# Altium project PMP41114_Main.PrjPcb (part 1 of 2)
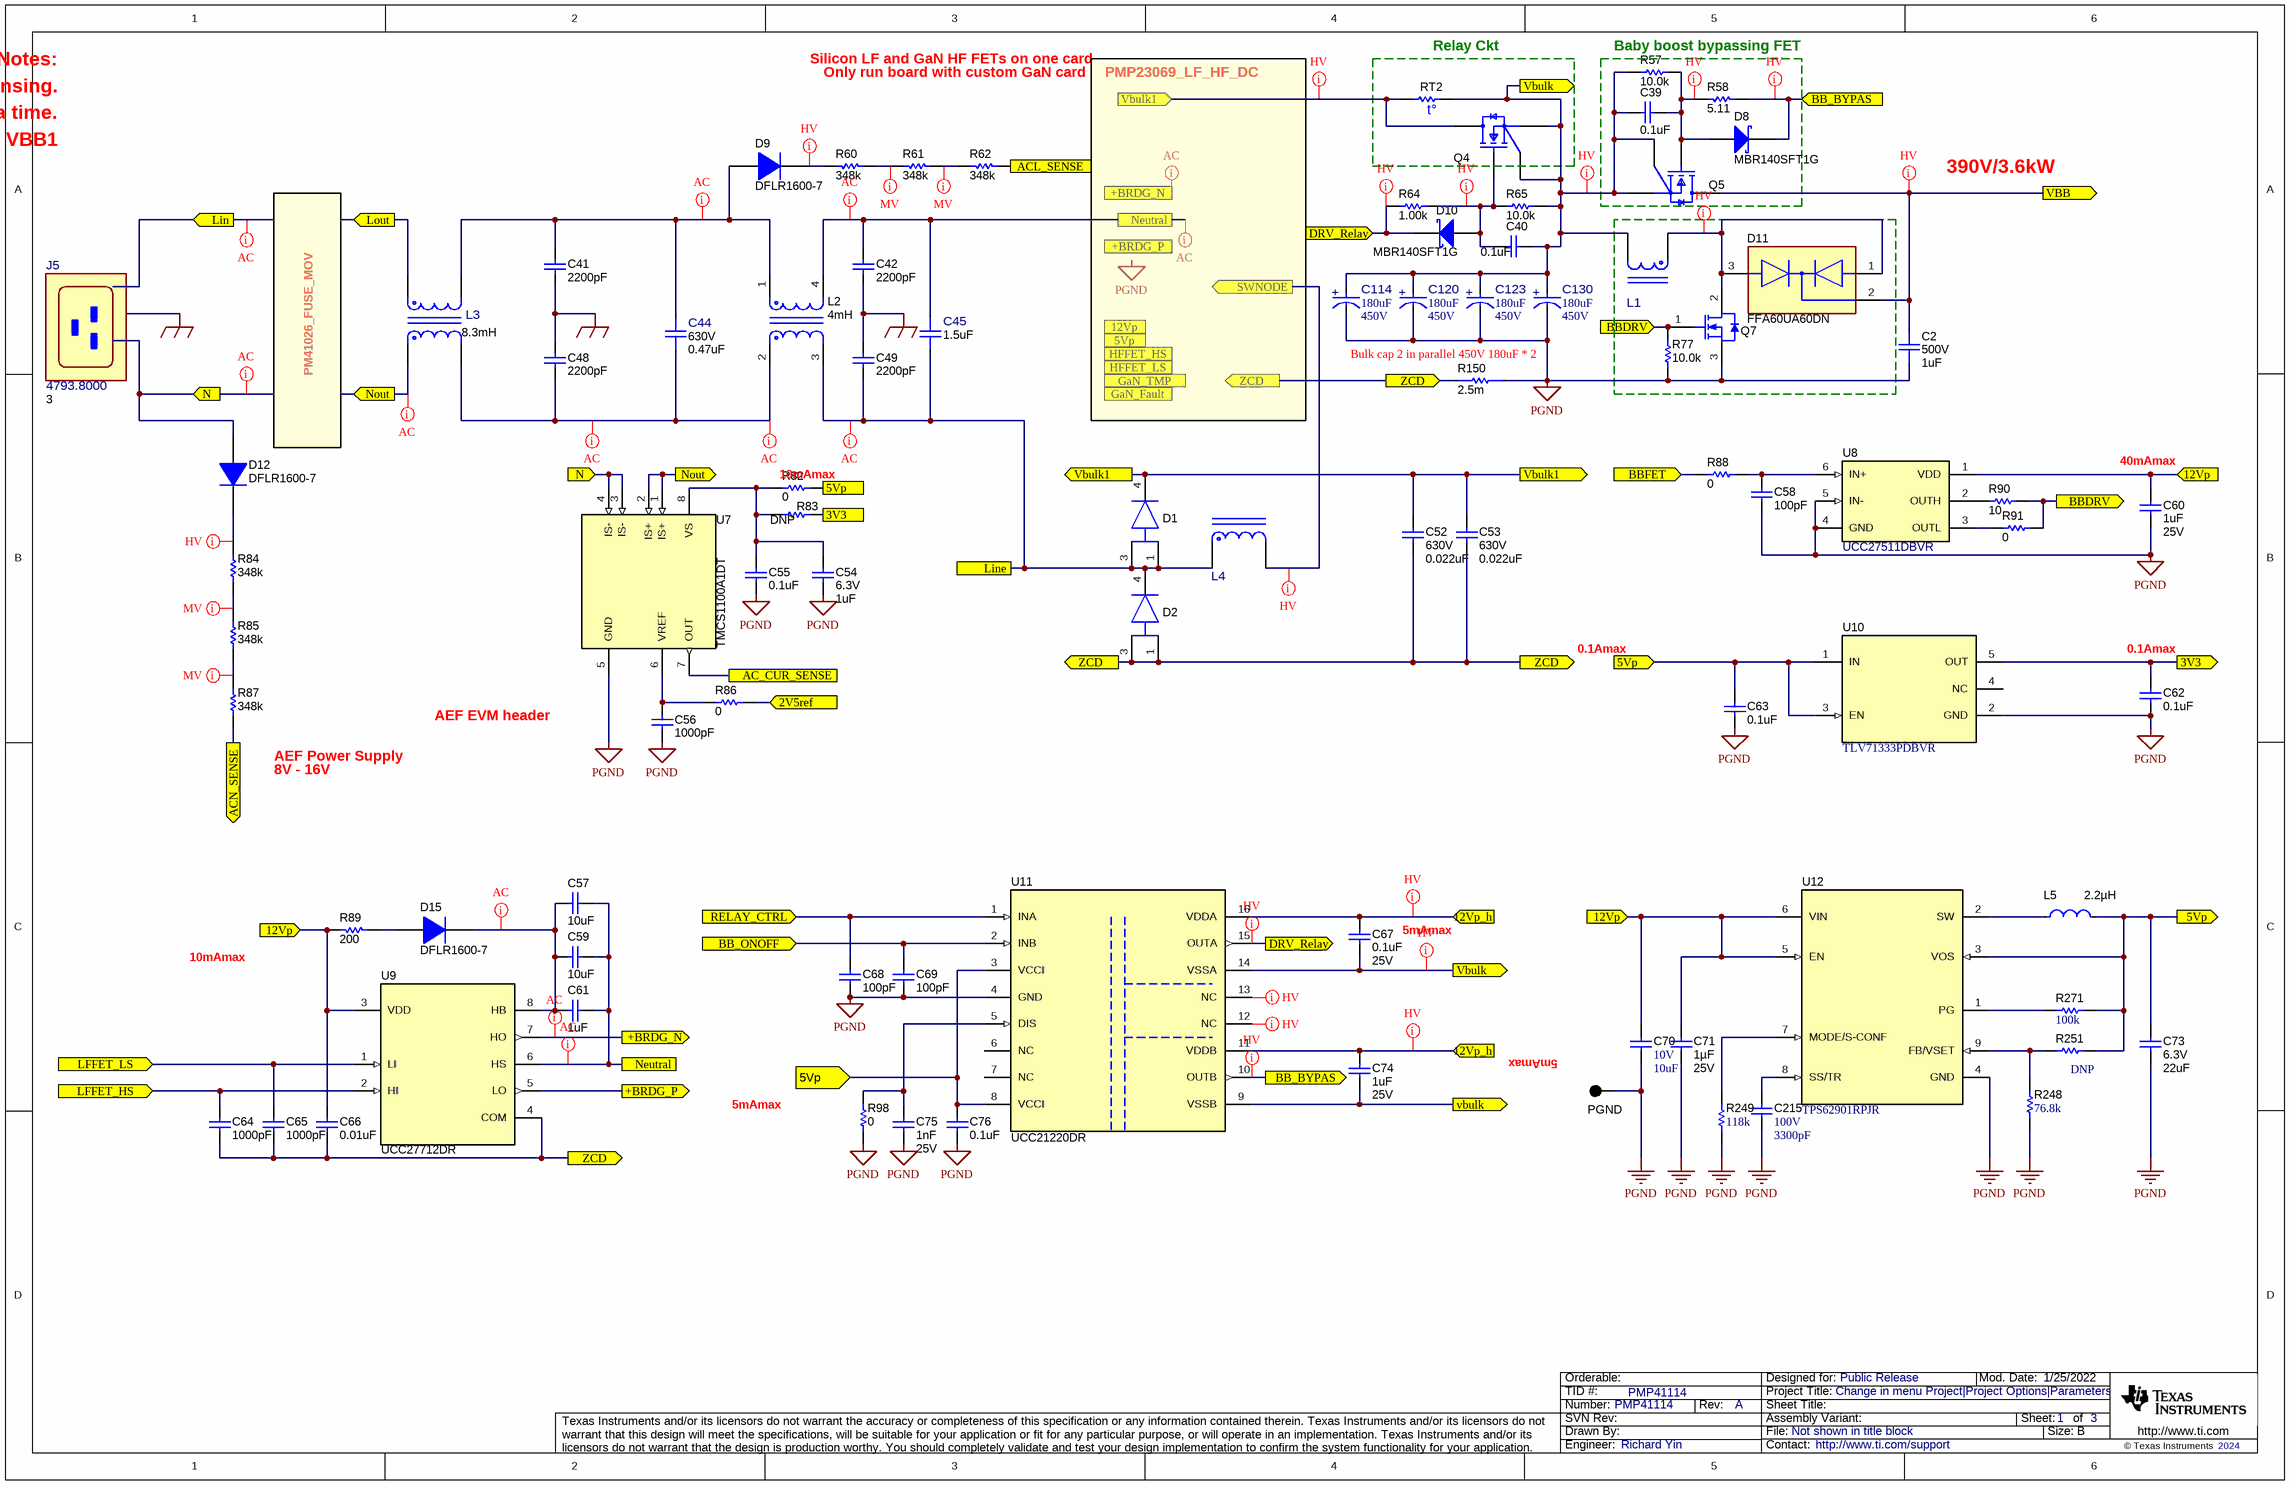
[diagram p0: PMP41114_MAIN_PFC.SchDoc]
CopyrightYear: 2024; PCB_Layout: Richard Yin; PCB_Rev: A; PRJ_Customer: Public Release; PRJ_Engineer: Richard Yin; PRJ_Number: PMP41114; PRJ_Title: Change in menu Project|Project Options|Parameters; SCH_Rev: A; TechSupport: http://www.ti.com/support; TID: PMP41114
3 sheets, 192 parts. Net scope: flat (ports and power ports of the same name join across sheets).
Board file: PMP41114_MAIN_PCB.PcbDoc
Sheets:
  PMP41114_MAIN_PFC.SchDoc
  PMP41114_MAIN_PFC_Control.SchDoc
  PMP41114_MAIN_LLC.SchDoc

## Sheet PMP41114_MAIN_PFC.SchDoc
size 431 x 279 mm; Date: Not shown in title block; ApprovedBy: Not shown in title block; CheckedBy: Not shown in title block; Author: Not shown in title block; CompanyName: Not shown in title block; Engineer: Not shown in title block; Organization: Not shown in title block; Address1: Not shown in title block; Address2: Not shown in title block; Address3: Not shown in title block; Address4: Not shown in title block; DocumentNumber: 1; Revision: Use project parameter SCH_Rev; SheetNumber: 1; SheetTotal: 3; PageSetup: Record=PageOptions¦CenterHorizontal=True¦CenterVertical=True¦PrintScale=1.00¦XCorrection=1.00¦YCorrection=1.00¦PrintKind=0¦BorderSize=5000000¦LeftOffset=0¦BottomOffset=0¦Orientation=2¦PaperLength=1000¦PaperWidth=1000¦Scale=100¦PaperSource=15¦PrintQuality=600¦MediaType=1¦DitherType=10¦PaperKind=Letter¦PrintScaleMode=1

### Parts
C2  VDC_V: 500V  ValueDisplayed: 1uF  [FP-B58031U5105M062_SMD2-MFG]  (hidden comment: B58031U5105M062)
C39  ValueDisplayed: 0.1uF  [0603]  (hidden comment: 06033C104JAT2A)
C40  ValueDisplayed: 0.1uF  [0603]  (hidden comment: 06033C104JAT2A)
C41  ValueDisplayed: 2200pF  [E_900x700x900]  (hidden comment: DE6E3KJ222MN3A)
C42  ValueDisplayed: 2200pF  [E_900x700x900]  (hidden comment: DE6E3KJ222MN3A)
C44  VDC_V: 630V  ValueDisplayed: 0.47uF  [FP-F862BY474K310Z_RADIAL-MFG]  (hidden comment: F862BY474K310Z)
C45  ValueDisplayed: 1.5uF  [FP-890334026030_RADIAL-MFG]  (hidden comment: 890334026030)
C48  ValueDisplayed: 2200pF  [E_900x700x900]  (hidden comment: DE6E3KJ222MN3A)
C49  ValueDisplayed: 2200pF  [E_900x700x900]  (hidden comment: DE6E3KJ222MN3A)
C52  VDC_V: 630V  ValueDisplayed: 0.022uF  [1210_150]  (hidden comment: GRM32QR72J223KW01L)
C53  VDC_V: 630V  ValueDisplayed: 0.022uF  [1210_150]  (hidden comment: GRM32QR72J223KW01L)
C54  VDC_V: 6.3V  ValueDisplayed: 1uF  [0402]  (hidden comment: GRM155R70J105KA12D)
C55  ValueDisplayed: 0.1uF  [0402]  (hidden comment: GRM155R70J104KA01D)
C56  ValueDisplayed: 1000pF  [0402]  (hidden comment: GRM155R60J102KA01D)
C57  ValueDisplayed: 10uF  [0805_HV]  (hidden comment: 0805YD106MAT2A)
C58  ValueDisplayed: 100pF  [0402]  (hidden comment: 0402YC101KAT2A)
C59  ValueDisplayed: 10uF  [0805_HV]  (hidden comment: 0805YD106MAT2A)
C60  ValueDisplayed: 1uF  Value2: 25V  [1206]  (hidden comment: C3216X7R1E105K085AA)
C61  ValueDisplayed: 1uF  [0603]  (hidden comment: C1608X7R1E105K080AB)
C62  ValueDisplayed: 0.1uF  [0402]  (hidden comment: GRM155R70J104KA01D)
C63  ValueDisplayed: 0.1uF  [0402]  (hidden comment: GRM155R70J104KA01D)
C64  ValueDisplayed: 1000pF  [0603]  (hidden comment: 06035A102KAT2A)
C65  ValueDisplayed: 1000pF  [0603]  (hidden comment: 06035A102KAT2A)
C66  ValueDisplayed: 0.01uF  [0603]  (hidden comment: C0603X103K5RACTU)
C67  ValueDisplayed: 0.1uF  VDC_V: 25V  [1206_190]  (hidden comment: C1206H104J3GACTU)
C68  ValueDisplayed: 100pF  [0402]  (hidden comment: 0402YC101KAT2A)
C69  ValueDisplayed: 100pF  [0402]  (hidden comment: 0402YC101KAT2A)
C70  VDC_V: 10V  ValueDisplayed: 10uF  [1206]  (hidden comment: C3216X7R1A106M160AC)
C71  Cap_F: 1µF  VDC_V: 25V  [0805_HV]  (hidden comment: C0805C105K3RACTU)
C73  VDC_V: 6.3V  ValueDisplayed: 22uF  [0805_HV]  (hidden comment: CL21A226KQQNNNE)
C74  ValueDisplayed: 1uF  Value2: 25V  [1206]  (hidden comment: C3216X7R1E105K085AA)
C75  Cap_F: 1nF  VDC_V: 25V  [0603]  (hidden comment: GRM188R71E102KA01D)
C76  ValueDisplayed: 0.1uF  [0402]  (hidden comment: 0402YC104KAT2A)
C114  ValueDisplayed: 180uF  VDC_V: 450V  [FP-450HXW180MEFR16X50_RADIAL-MFG]  (hidden comment: 450HXW180MEFR16X50)
C120  ValueDisplayed: 180uF  VDC_V: 450V  [FP-450HXW180MEFR16X50_RADIAL-MFG]  (hidden comment: 450HXW180MEFR16X50)
C123  ValueDisplayed: 180uF  VDC_V: 450V  [FP-450HXW180MEFR16X50_RADIAL-MFG]  (hidden comment: 450HXW180MEFR16X50)
C130  ValueDisplayed: 180uF  VDC_V: 450V  [FP-450HXW180MEFR16X50_RADIAL-MFG]  (hidden comment: 450HXW180MEFR16X50)
C215  VDC_V: 100V  ValueDisplayed: 3300pF  [0402]  (hidden comment: GRM155R72A332KA01D)
D1  VS-15EVL06-M3/I  [FP-VS-15AWL06FN-M3_D-PAK (TO-252AA)-MFG]  (value not drawn)
D2  VS-15EVL06-M3/I  [FP-VS-15AWL06FN-M3_D-PAK (TO-252AA)-MFG]  (value not drawn)
D8  MBR140SFT1G  [SOD-123FL]
D9  DFLR1600-7  [PowerDI123]
D10  MBR140SFT1G  [SOD-123FL]
D11  FFA60UA60DN  [FP-FFA60UA60DN_SC-65-MFG]
D12  DFLR1600-7  [PowerDI123]
D15  DFLR1600-7  [PowerDI123]
J5  4793.8000  PinCount: 3  [FP-4793.8000_RCPT_IEC320-C20-MFG]
L1  PAL6598.104NLT  [FP-PAL6281.104NL_PTH_20MM5_11MM0-MFG]  (value not drawn)
L2  Ind_H: 4mH  [FP-PAC6270NL_PTH_TRANSFORMER_30MM0_19MM0-MFG]  (hidden comment: PAC6596NL)
L3  Ind_H: 8.3mH  [FP-PAC6280NL_PTH_25MM0_12MM5-MFG]  (hidden comment: PAC6597NL)
L4  PAL6585  [FP-PAL6269NL_PTH_32MM0_27MM8-MFG]  (value not drawn)
L5  Ind_H: 2.2µH  [FP-74438336010_SMD2-MFG]  (hidden comment: 74438336022)
PGND  5001  [Keystone5001]  (value not drawn)
Q4  IPT60R022S7XTMA1  [FP-IPT60R080G7XTMA1_HSOF-8-MFG]  (value not drawn)
Q5  IPT60R022S7XTMA1  [FP-IPT60R080G7XTMA1_HSOF-8-MFG]  (value not drawn)
Q7  IPP60R060P7XKSA1  [TO-220AB_100mil]  (value not drawn)
R57  ValueDisplayed: 10.0k  [0603]  (hidden comment: CRCW060310K0FKEA)
R58  ValueDisplayed: 5.11  [0603]  (hidden comment: CRCW06035R11FKEA)
R60  ValueDisplayed: 348k  [1206]  (hidden comment: RC1206FR-07348KL)
R61  ValueDisplayed: 348k  [1206]  (hidden comment: RC1206FR-07348KL)
R62  ValueDisplayed: 348k  [1206]  (hidden comment: RC1206FR-07348KL)
R64  ValueDisplayed: 1.00k  [1206]  (hidden comment: ERJ-8ENF1001V)
R65  ValueDisplayed: 10.0k  [0603]  (hidden comment: CRCW060310K0FKEA)
R77  ValueDisplayed: 10.0k  [0603]  (hidden comment: CRCW060310K0FKEA)
R82  ValueDisplayed: 0  [0402]  (hidden comment: RC0402JR-070RL)
R83  value DNP  [0402]  (hidden comment: RC0402JR-070RL)
R84  ValueDisplayed: 348k  [1206]  (hidden comment: RC1206FR-07348KL)
R85  ValueDisplayed: 348k  [1206]  (hidden comment: RC1206FR-07348KL)
R86  ValueDisplayed: 0  [0402]  (hidden comment: RC0402JR-070RL)
R87  ValueDisplayed: 348k  [1206]  (hidden comment: RC1206FR-07348KL)
R88  ValueDisplayed: 0  [0402]  (hidden comment: CRCW04020000Z0ED)
R89  value 200  [0603]  (hidden comment: CRCW0603200RFKEA)
R90  ValueDisplayed: 10  [0603]  (hidden comment: CRCW060310R0JNEAHP)
R91  ValueDisplayed: 0  [0603]  (hidden comment: CRCW06030000Z0EA)
R98  ValueDisplayed: 0  [0603]  (hidden comment: CRCW06030000Z0EA)
R150  value 2.5m  [FP-WSLP3921L1000FEA_3921-MFG]  (hidden comment: WSLP39212L500FEA)
R248  ValueDisplayed: 76.8k  [0402]  (hidden comment: CRCW040276K8FKED)
R249  ValueDisplayed: 118k  [0603]  (hidden comment: CRCW0603118KFKEA)
R251  value DNP  [0402]  (hidden comment: RC0402FR-07100KL)
R271  ValueDisplayed: 100k  [0402]  (hidden comment: RC0402FR-07100KL)
RT2  B59751B0120A070  [TDK_B751]  (value not drawn)
U7  TMCS1100A1DT  [D0008A_N]
U8  UCC27511DBVR  [DBV0006A_N]
U9  UCC27712DR  [D0008A_N]
U10  TLV71333PDBVR  [DBV0005A_N]
U11  UCC21220DR  [D0016B]
U12  TPS62901RPJR  [RPJ0009A]

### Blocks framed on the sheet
Relay Ckt: Q4 RT2
Baby boost bypassing FET: C39 D8 Q5 R57 R58

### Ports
2V5ref (in), 3V3 (in), 3V3 (out), 5Vp (in), 5Vp (out), 12Vp (in), 12Vp_h (in), +BRDG_N (in), +BRDG_N (out), +BRDG_P (in), +BRDG_P (out), AC_CUR_SENSE, ACL_SENSE (out), ACN_SENSE (out), BB_BYPAS (in), BB_BYPAS (out), BB_ONOFF (in), BBDRV (in), BBDRV (out), BBFET (in), DRV_Relay (in), DRV_Relay (out), GaN_Fault (out), GaN_TMP (out), HFFET_HS (in), HFFET_LS (in), LFFET_HS (in), LFFET_LS (in), Lin (in), Line, Lout (in), N (in), Neutral, Nout (in), Nout (out), RELAY_CTRL (in), SWNODE (out), VBB (out), Vbulk1 (in), Vbulk1 (out), Vbulk (out), vbulk (out), ZCD (out)

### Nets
3V3: C62.1 R83.2 U10.5(OUT) ; port 3V3
12VP: C60.1 C66.1 C70.1 C71.1 R89.2 U8.1(VDD) U9.3(VDD) U12.5(EN) U12.6(VIN) ; port 12Vp
12Vp_h: C67.2 C74.1 U11.11(VDDB) U11.16(VDDA) ; port 12Vp_h
PE: C41.1 C42.1 C48.2 C49.2
PGND: C2.1 C54.2 C55.2 C56.2 C58.2 C60.2 C62.2 C63.2 C68.2 C69.2 C70.2 C71.2 C73.2 C75.2 C76.2 C114.1(CATHODE) C120.1(CATHODE) C123.1(CATHODE) C130.1(CATHODE) C215.2 PGND.1 Q7.3(S) R77.1 R98.1 R150.1 R248.1 R249.1 U7.5(GND) U8.4(GND) U8.5(IN-) U10.2(GND) U11.4(GND) U12.4(GND)
2V5ref: R86.2 ; port 2V5ref
5Vp: C63.1 C73.1 C76.1 L5.2 R82.2 R251.2 R271.2 U10.1(IN) U10.3(EN) U11.3(VCCI) U11.8(VCCI) U12.3(VOS) ; port 5Vp
+BRDG_N: U9.7(HO) ; port +BRDG_N
+BRDG_P: U9.5(LO) ; port +BRDG_P
AC_CUR_SENSE: U7.7(OUT) ; port AC_CUR_SENSE
ACL_SENSE: R62.1 ; port ACL_SENSE
ACN_SENSE: R87.1 ; port ACN_SENSE
BB_BYPAS: D8.1(K) R58.2 U11.10(OUTB) ; port BB_BYPAS
BB_ONOFF: C69.1 U11.2(INB) ; port BB_ONOFF
BBDRV: Q7.1(G) R77.2 R90.1 R91.2 ; port BBDRV
BBFET: R88.1 ; port BBFET
DRV_Relay: D10.1(K) R64.1 U11.15(OUTA) ; port DRV_Relay
LFFET_HS: C64.1 U9.2(HI) ; port LFFET_HS
LFFET_LS: C65.1 U9.1(LI) ; port LFFET_LS
Line: C45.2 C49.1 D1.1(Anode) D1.3(Anode) D2.4(Cathode) L2.3 L4.1 ; port Line
Lout: L3.2 ; port Lout
N: D12.2(A) U7.3(IS-) U7.4(IS-) ; port N
Neutral: C42.2 C45.1 C57.2 C59.2 C61.1 L2.4 U9.6(HS) ; port Neutral
Nout: L3.1 U7.1(IS+) U7.2(IS+) ; port Nout
RELAY_CTRL: C68.1 U11.1(INA) ; port RELAY_CTRL
SWNODE: L4.2 ; port SWNODE
VBB: C2.2 D11.2(COMMON_CATHODE) Q5.9(Drain) ; port VBB
Vbulk: C39.2 C40.1 C67.1 C74.2 C114.2(ANODE) C120.2(ANODE) C123.2(ANODE) C130.2(ANODE) L1.2(F) Q4.2(Driver_Source) Q4.3-4-5-6-7-8(Source) Q5.2(Driver_Source) Q5.3-4-5-6-7-8(Source) R57.1 R65.2 RT2.2 U11.9(VSSB) U11.14(VSSA) ; port Vbulk, port vbulk
Vbulk1: C52.1 C53.1 D1.4(Cathode) Q4.9(Drain) RT2.1 ; port Vbulk1
ZCD: C52.2 C53.2 C64.2 C65.2 C66.2 D2.1(Anode) D2.3(Anode) R150.2 U9.4(COM) ; port ZCD
NetC39_1: C39.1 D8.2(A) Q5.1(Gate) R57.2 R58.1
NetC40_2: C40.2 D10.2(A) Q4.1(Gate) R64.2 R65.1
NetC41_2: C41.2 C44.2 D9.2(A) L2.1 L3.3
NetC44_1: C44.1 C48.1 L2.2 L3.4
NetC54_1: C54.1 C55.1 R82.1 R83.1 U7.8(VS)
NetC56_1: C56.1 R86.1 U7.6(VREF)
NetC57_1: C57.1 C59.1 C61.2 D15.1(K) U9.8(HB)
NetC58_1: C58.1 R88.2 U8.6(IN+)
NetC75_1: C75.1 R98.2 U11.5(DIS)
NetC215_1: C215.1 U12.8(SS/TR)
NetD9_1: D9.1(K) R60.2
NetD11_1: D11.1(1_ANODE) D11.3(2_ANODE) L1.1(S) Q7.2(D)
NetD12_1: D12.1(K) R84.2
NetD15_2: D15.2(A) R89.1
NetL5_1: L5.1 U12.2(SW)
NetR60_1: R60.1 R61.2
NetR61_1: R61.1 R62.2
NetR84_1: R84.1 R85.2
NetR85_1: R85.1 R87.2
NetR90_2: R90.2 U8.2(OUTH)
NetR91_1: R91.1 U8.3(OUTL)
NetR248_2: R248.2 R251.1 U12.9(FB/VSET)
NetR249_2: R249.2 U12.7(MODE/S-CONF)
NetR271_1: R271.1 U12.1(PG)

Not connected (* = marked no-connect by the designer): U10 4(NC); U11 6(NC) 7(NC) 12(NC) 13(NC)

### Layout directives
net class MV: NetR60_1, NetR61_1, NetR84_1, NetR85_1
net class HV: 12Vp_h, BB_BYPAS, DRV_Relay, NetC39_1, NetC40_2, NetD9_1, NetD11_1, NetD12_1, NetU11_12, NetU11_13, SWNODE, VBB, Vbulk, Vbulk1
net class AC: +BRDG_N, Lin, Line, N, NetC41_2, NetC44_1, NetC57_1, Neutral, Nout

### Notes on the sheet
- Assembly Notes:
- 1. Transformer winding go through CT100 for current sensing.
- Silicon LF and GaN HF FETs on one card
- Only run board with custom GaN card
- PMP23069_LF_HF_DC
- 2. Use either LMG3x2xR030 EVM or customized daughter card at a time.
- 3. A jump wire is needed between VBB and VBB1
- 390V/3.6kW
- PM41026_FUSE_MOV
- (near R150) Bulk cap 2 in parallel 450V 180uF * 2
- 10mAmax
- (near C60) 40mAmax
- 0.1Amax
- (near C62) 0.1Amax
- (near R87) AEF Power Supply
- 8V - 16V
- AEF EVM header
- 5mAmax
- (near R98) 5mAmax
- Labels drawn without touching a wire or pin: PGND

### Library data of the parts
C2 = CMP-0091050-1: TDK 1µF Multilayer Ceramic Capacitor MLCC 500V dc ±20% SMD; AEC Grade: Grade 0; AEC Qualified: Yes; SizeZ_mm: 4.5mm
C39 C40 = CMP-0006752-5: CAP, CERM, 0.1 uF, 25 V, +/- 5%, X7R, 0603; Manufacturer: AVX; Polarized: N; Value: 0.1uF; U/M: EA; Cap_F: 100nF; ESR_ohm: 0.05; Value1: 0.05 ohm; VDC_V: 25V; TaMin_C: -55°C; TaMax_C: 125°C; AEC Category: Q200; SizeArea_mm2: 1.28; SizeAreaWB_mm2: 4.68; SizeX_mm: 1.6; SizeY_mm: 0.8; SizeZ_mm: 1
C41 C42 C48 C49 = CMP-0009613-2: CAP, CERM, 2200 pF, 300 V, +/- 20%, E, TH, 2- Leads, Body 9x7mm, Pin Spacing 7.5mm; Manufacturer: MuRata; Polarized: N; Value: 2200pF; U/M: EA; Cap_F: 2.2nF; Value1: Unknown; VDC_V: 300V; TaMin_C: -40°C; TaMax_C: 125°C; Cap_Case: 9x7x9mm; SizeArea_mm2: 63; SizeAreaWB_mm2: 99; SizeX_mm: 9; SizeY_mm: 7; SizeZ_mm: 12; AEC Category: Q200
C44 = CMP-0090549-1: 0.47µF Film Capacitor 310V 630V Polypropylene (PP), Metallized Radial; Manufacturer: Kemet; AEC Qualified: Yes; Tolerance_%: 10%; Value: 470nF; AEC Grade: Grade 2; SizeZ_mm: 19mm; Standoff Height: 0.5mm
C45 = CMP-0093436-1: 1.5 µF Film Capacitor 310V - Polypropylene (PP), Metallized Radial; Manufacturer: Wurth Electronics; Value: 1.5µF; SizeZ_mm: 21.5mm; AEC Qualified: No; Tolerance_%: 10%; VAC_X: X2
C52 C53 = CMP-0009248-2: CAP, CERM, 0.022 uF, 630 V, +/- 10%, X7R, 1210; Manufacturer: MuRata; TaMin_C: -55°C; Polarized: N; SizeAreaWB_mm2: 14.7; Value1: Unknown; U/M: EA; TaMax_C: 125°C; SizeZ_mm: 1.5; SizeX_mm: 3.2; SizeY_mm: 2.5; Cap_Case: 1210; SizeArea_mm2: 8; Cap_F: 22nF; AEC Category: Q200
C54 = CMP-0064947-2: CAP, CERM, 1 uF, 6.3 V,+/- 10%, X7R, 0402; Manufacturer: MuRata; TaMin_C: -55°C; Polarized: N; SizeAreaWB_mm2: 3; Value1: Unknown; U/M: EA; Value: 1uF; TaMax_C: 125°C; SizeZ_mm: 0.6; SizeX_mm: 1; SizeY_mm: 0.5; Cap_F: 1µF; AEC Category: Q200
C55 C62 C63 = CMP-0006623-2: CAP, CERM, 0.1 uF, 6.3 V, +/- 10%, X7R, 0402; Manufacturer: MuRata; Polarized: N; Value: 0.1uF; U/M: EA; Cap_F: 100nF; Value1: Unknown; VDC_V: 6.3V; TaMin_C: -55°C; TaMax_C: 125°C; AEC Category: Q200; SizeArea_mm2: 0.5; SizeAreaWB_mm2: 3; SizeX_mm: 1; SizeZ_mm: 0.6
C56 = CMP-0006529-2: CAP, CERM, 1000 pF, 6.3 V, +/- 10%, X5R, 0402; Manufacturer: MuRata; Polarized: N; Value: 1000pF; U/M: EA; Cap_F: 1nF; Value1: Unknown; VDC_V: 6.3V; TaMin_C: -55°C; TaMax_C: 85°C; AEC Category: Q200; SizeArea_mm2: 0.5; SizeAreaWB_mm2: 3; SizeX_mm: 1; SizeZ_mm: 0.6
C57 C59 = CMP-0007678-2: CAP, CERM, 10 uF, 16 V, +/- 20%, X5R, 0805; Manufacturer: AVX; Polarized: N; Value: 10uF; U/M: EA; Cap_F: 10µF; Value1: Unknown; VDC_V: 16V; TaMin_C: -55°C; TaMax_C: 85°C; Cap_Case: 0805; AEC Category: Q200; SizeArea_mm2: 2.5; SizeAreaWB_mm2: 6.75; SizeX_mm: 2; SizeY_mm: 1.25; SizeZ_mm: 1.45
C58 C68 C69 = CMP-0006200-2: CAP, CERM, 100 pF, 16 V, +/- 10%, X7R, 0402; Manufacturer: AVX; Polarized: N; Value: 100pF; U/M: EA; Value1: Unknown; VDC_V: 16V; TaMin_C: -55°C; TaMax_C: 125°C; SizeArea_mm2: 0.5; SizeAreaWB_mm2: 3; SizeX_mm: 1; SizeZ_mm: 0.6; AEC Category: Q200
C60 C74 = CMP-0008691-2: CAP, CERM, 1 uF, 25 V, +/- 10%, X7R, 1206; Manufacturer: TDK; Polarized: N; Value: 1uF; U/M: EA; Cap_F: 1µF; ESR_ohm: 0.01; Value1: 0.01 ohm; TaMin_C: -55°C; TaMax_C: 125°C; SizeArea_mm2: 5.12; SizeAreaWB_mm2: 10.92; SizeX_mm: 3.2; SizeY_mm: 1.6; SizeZ_mm: 1.35; AEC Category: Q200
C61 = CMP-0007040-4: CAP, CERM, 1 uF, 25 V, +/- 10%, X7R, 0603; Manufacturer: TDK; Polarized: N; Value: 1uF; U/M: EA; Cap_F: 1µF; Value1: Unknown; VDC_V: 25V; TaMin_C: -55°C; TaMax_C: 125°C; AEC Category: Q200; SizeArea_mm2: 1.28; SizeAreaWB_mm2: 4.68; SizeX_mm: 1.6; SizeY_mm: 0.8; SizeZ_mm: 1
C64 C65 = CMP-0006764-4: CAP, CERM, 1000 pF, 50 V, +/- 10%, C0G/NP0, 0603; Manufacturer: AVX; Polarized: N; Value: 1000pF; U/M: EA; Cap_F: 1nF; ESR_ohm: 0.048; Value1: 0.048 ohm; VDC_V: 50V; TaMin_C: -55°C; TaMax_C: 125°C; SizeArea_mm2: 1.28; SizeAreaWB_mm2: 4.68; SizeX_mm: 1.6; SizeY_mm: 0.8; SizeZ_mm: 1; AEC Category: Q200
C66 = CMP-0006978-4: CAP, CERM, 0.01 uF, 50 V, +/- 10%, X7R, 0603; Manufacturer: Kemet; Polarized: N; Value: 0.01uF; U/M: EA; Cap_F: 10nF; Value1: Unknown; VDC_V: 50V; TaMin_C: -55°C; TaMax_C: 125°C; AEC Category: Q200; SizeArea_mm2: 1.28; SizeAreaWB_mm2: 4.68; SizeX_mm: 1.6; SizeY_mm: 0.8; SizeZ_mm: 1
C67 = CMP-0008641-2: CAP, CERM, 0.1 uF, 25 V, +/- 5%, C0G/NP0, 1206_190; Manufacturer: Kemet; Polarized: N; Value: 0.1uF; U/M: EA; Cap_F: 100nF; Value1: Unknown; TaMin_C: -55°C; TaMax_C: 200°C; Cap_Case: 1206; AEC Category: Q200; SizeArea_mm2: 5.12; SizeAreaWB_mm2: 10.92; SizeX_mm: 3.2; SizeY_mm: 1.6; SizeZ_mm: 1.9
C70 = CMP-0008689-2: CAP, CERM, 10 uF, 10 V, +/- 20%, X7R, 1206; Manufacturer: TDK; TaMin_C: -55°C; ESR_ohm: 4.6m; Polarized: N; SizeAreaWB_mm2: 10.92; Value1: 0.0046 ohm; U/M: EA; Value: 10uF; TaMax_C: 125°C; SizeZ_mm: 1.35; SizeX_mm: 3.2; SizeY_mm: 1.6; SizeArea_mm2: 5.12; CompType: Capacitor; Cap_F: 10µF; AEC Category: Q200
C71 = CMP-0007728-2: CAP, CERM, 1 uF, 25 V, +/- 10%, X7R, 0805; Manufacturer: Kemet; TaMin_C: -55°C; Polarized: N; SizeAreaWB_mm2: 6.75; Value1: Unknown; U/M: EA; Value: 1uF; TaMax_C: 125°C; SizeZ_mm: 1.45; SizeX_mm: 2; SizeY_mm: 1.25; Cap_Case: 0805; SizeArea_mm2: 2.5; CompType: Capacitor; AEC Category: Q200
C73 = CMP-0007989-2: CAP, CERM, 22 uF, 6.3 V, +/- 10%, X5R, 0805; Manufacturer: Samsung Electro-Mechanics; TaMin_C: -55°C; Polarized: N; SizeAreaWB_mm2: 6.75; Value1: Unknown; U/M: EA; Value: 22uF; TaMax_C: 85°C; SizeZ_mm: 1.45; SizeX_mm: 2; SizeY_mm: 1.25; Cap_Case: 0805; SizeArea_mm2: 2.5; CompType: Capacitor; Cap_F: 22µF; AEC Category: Q200
C75 = CMP-0007402-5: CAP, CERM, 1000 pF, 25 V, +/- 10%, X7R, 0603; Manufacturer: MuRata; TaMin_C: -55°C; Polarized: N; SizeAreaWB_mm2: 4.68; Value1: Unknown; U/M: EA; Value: 1000pF; TaMax_C: 125°C; SizeZ_mm: 1; SizeX_mm: 1.6; SizeY_mm: 0.8; SizeArea_mm2: 1.28; AEC Category: Q200; MFG_Status: TI_Obsolete
C76 = CMP-0006201-2: CAP, CERM, 0.1 uF, 16 V, +/- 10%, X7R, 0402; Manufacturer: AVX; Polarized: N; Value: 0.1uF; U/M: EA; Cap_F: 100nF; Value1: Unknown; VDC_V: 16V; TaMin_C: -55°C; TaMax_C: 125°C; SizeArea_mm2: 0.5; SizeAreaWB_mm2: 3; SizeX_mm: 1; SizeZ_mm: 0.6; AEC Category: Q200
C114 C120 C123 C130 = CMP-0098127-1: 180 µF 450 V Aluminum Electrolytic Capacitors Radial, Can 3000 Hrs @ 105°C; Manufacturer: Rubycon; Tolerance_%: 20%; SizeZ_mm: 52mm; Life: 3000Hours; Dissipation Factor: 25%; AEC Qualified: No; Cap_F: 180µF; Value: 180µF; Leakage Current: 853.8uA; IRMS_A: 1.15A
C215 = CMP-0006708-2: CAP, CERM, 3300 pF, 100 V, +/- 10%, X7R, 0402; Manufacturer: MuRata; TaMin_C: -55°C; Polarized: N; SizeAreaWB_mm2: 3; Value1: Unknown; U/M: EA; Value: 3300pF; TaMax_C: 125°C; SizeZ_mm: 0.6; SizeX_mm: 1; SizeY_mm: 0.5; Cap_F: 3.3nF; AEC Category: Q200
D1 D2 = CMP-0086603-1: DIODE GEN PURPOSE 600V SLIMDPAK; Manufacturer: Vishay; TJmax_C: 175°C; SizeZ_mm: 2.52mm; AEC Qualified: No
D8 D10 = CMP-0028548-2: Diode, Schottky, 40 V, 1 A, SOD-123FL; Manufacturer: ON Semiconductor; SizeZ_mm: 0.98; Vf_V: 5.5dV; AEC Category: Q101; Green_REACh: Passed; SizeArea_mm2: 5.94; Vr_V: 40V; TJmax_C: 125°C; RJC_CperW: 26; Value1: 1A; SizeY_mm: 1.65; SizeX_mm: 3.6; Value: 40V; Value2: 0.55V; SizeAreaWB_mm2: 12.19; Green_Lifecycle: Active
D9 D12 D15 = CMP-0076978-2: Diode, Standard Recovery Rectifier, 600 V, 1 A, PowerDI123; Manufacturer: Diodes Inc.; AEC Category: Q101; SizeAreaWB_mm2: 13.066; SizeY_mm: 1.78; Value2: 1.1V; TJmax_C: 150°C; Green_Lifecycle: Not Set; Value1: 1A; Value: 600V; SizeZ_mm: 0.98; SizeX_mm: 3.7; SizeArea_mm2: 6.586; Green_REACh: Incomplete
D11 = CMP-0090872-1: Diode Array 1 Pair Common Cathode Standard 600V 30A Through Hole TO-3P-3, SC-65-3; Manufacturer: ON Semiconductor; Peak Reverse Current: 100uA; SizeZ_mm: 23.8mm; AEC Qualified: No; TJmax_C: 175°C; Max Surge Forward Current: 180A; Standoff Height: 3.3mm
J5 = CMP-0122913-1: Power Entry Connector Receptacle, Male Blades IEC 320-C20 Panel Mount, Snap-In; Manufacturer: Schurter; Current_A: 20A; Voltage_V: 250V; AEC Qualified: No
L1 = CMP-0091020-1: Inductor Buck/Boost, Toroid, TH, 100uH 15% 8A; Manufacturer: Pulse Electronics; DCR_ohm: 0.108; AEC Qualified: No; SizeZ_mm: 22.5mm; Test Frequency: 100kHz; Ind_H: 100µH
L2 = CMP-0091106-1: IND, CUR-SENSE, 4MH, 20A, TOR, TH; Manufacturer: Pulse Electronics; DCR_ohm: 6m; Voltage_Isolation_Vrms: 1500VDC; AEC Qualified: No; SizeZ_mm: 32mm; Rsec1_ohm: 6mΩ; Ns1toNp: 1:1
L3 = CMP-0091125-1: INDUCTOR CUR-SENSE 8.3mH TOR TH; Manufacturer: Pulse Electronics; Tolerance_%: 30%; AEC Qualified: No; SizeZ_mm: 24.5mm; Test Frequency: 10kHz; DCR_ohm: 0.012
L4 = CMP-0091118-1: Inductor Power 300uH; Manufacturer: Pulse Electronics; Tolerance_%: 15%; Test Frequency: 100kHz; Ind_H: 300µH; DCR_ohm: 0.075; SizeZ_mm: 30.5mm
L5 = CMP-0087867-1: 2.2µH Shielded Molded Inductor 2.4A 67mOhm Max 2-SMD; Manufacturer: Wurth Electronics; SizeZ_mm: 2mm; Material: Metal Composite; Isat: 4.3A; Symbol Name: SYM-74438336010; DCR_ohm: 0.032; AEC Grade: Grade 1; AEC Qualified: Yes
PGND = 5001: Test Point, Miniature, Black, TH; Manufacturer: Keystone; CompType: Test Point Loop; ContactFinish: Silver; Green_Lifecycle: Active; Green_REACh: Passed
Q4 Q5 = CMP-0086487-1: N-Channel 600V 23A (Tc) 390W (Tc) Surface Mount PG-HSOF-8-2; Manufacturer: Infineon; VdsMax_V: 650V; IdsMax_A: 29A; Vgs_V: 20V; AEC Qualified: No; ChMode: False; SizeZ_mm: 2.4mm
Q7 = CMP-0001223-3: MOSFET N-CH 600V 48A TO220-3; Alternate Manufacturer: None; Manufacturer: Infineon Technologies; ChType: N; AEC Category: Q101; U/M: EA
R57 R65 R77 = CMP-0021998-4: RES, 10.0 k, 1%, 0.1 W, AEC-Q200 Grade 0, 0603; Manufacturer: Vishay-Dale; Value: 10.0k; Res_ohm: 10k; Value_Code: 10k0; Power_W: 100mW; Value2: 0.1W; VDC_V: 75V; TempCo: 100 ppm/C; SizeArea_mm2: 1.28; SizeX_mm: 1.6; SizeY_mm: 0.8; SizeZ_mm: 1; EIA_Code: E96; AEC Category: Q200; AEC Qualified: Y; AEC Grade: 0
R58 = CMP-0022523-4: RES, 5.11, 1%, 0.1 W, AEC-Q200 Grade 0, 0603; Manufacturer: Vishay-Dale; Value: 5.11; Value_Code: 5R11; Power_W: 100mW; Value2: 0.1W; VDC_V: 75V; TempCo: 100 ppm/C; SizeArea_mm2: 1.28; SizeX_mm: 1.6; SizeY_mm: 0.8; SizeZ_mm: 1; EIA_Code: E96; AEC Category: Q200; AEC Qualified: Y; AEC Grade: 0
R60-R62 R84 R85 R87 = CMP-0018215-2: RES, 348 k, 1%, 0.25 W, 1206; Manufacturer: Yageo America; Power_W: 250mW; TempCo: 100 ppm/C; U/M: EA; Value: 348k; EIA_Code: E96; SizeX_mm: 3.2; SizeY_mm: 1.6; SizeZ_mm: 1.35; Value2: 0.25W; SizeArea_mm2: 5.12; VDC_V: 200V; AEC Category: Q200
R64 = CMP-0017283-3: RES, 1.00 k, 1%, 0.25 W, AEC-Q200 Grade 0, 1206; Manufacturer: Panasonic; Value: 1.00k; Res_ohm: 1k; Value_Code: 1k00; Power_W: 250mW; Value2: 0.25W; VDC_V: 200V; TempCo: 100 ppm/C; SizeArea_mm2: 5.12; SizeX_mm: 3.2; SizeY_mm: 1.6; SizeZ_mm: 1.35; EIA_Code: E96; AEC Category: Q200; AEC Qualified: Y; AEC Grade: 0; SizeAreaWB_mm2: 10.92
R82 R86 = CMP-0027004-2: RES, 0, 5%, 0.063 W, 0402; Manufacturer: Yageo America; Power_W: 63mW; TempCo: 200 ppm/C; Value_Code: 0000; U/M: EA; Value: 0; EIA_Code: E24; SizeX_mm: 1; SizeY_mm: 0.5; SizeZ_mm: 0.6; Value2: 0.063W; VDC_V: 50V; AEC Category: Q200
R83 = CMP-0027004-2: Manufacturer: Yageo America; Power_W: 63mW; TempCo: 200 ppm/C; Value_Code: 0000; Value1: 5%; U/M: EA; EIA_Code: E24; Res_ohm: 0; SizeX_mm: 1; SizeY_mm: 0.5; SizeZ_mm: 0.6; Value2: 0.063W; VDC_V: 50V; AEC Category: Q200
R88 = CMP-0026822-3: RES, 0, 5%, 0.063 W, AEC-Q200 Grade 0, 0402; Manufacturer: Vishay-Dale; Value: 0; Value_Code: 0000; Power_W: 63mW; Value2: 0.063W; VDC_V: 50V; TempCo: 200 ppm/C; SizeArea_mm2: 0.5; SizeX_mm: 1; SizeZ_mm: 0.6; EIA_Code: E24; AEC Category: Q200; AEC Qualified: Y
R89 = CMP-0022201-5: RES, 200, 1%, 0.1 W, AEC-Q200 Grade 0, 0603; Manufacturer: Vishay-Dale; Value_Code: 200R; Power_W: 100mW; Value2: 0.1W; VDC_V: 75V; TempCo: 100 ppm/C; EIA_Code: E96; AEC Category: Q200; AEC Grade: 0; AEC Qualified: Y; SizeArea_mm2: 1.28; SizeX_mm: 1.6; SizeY_mm: 0.8; SizeZ_mm: 1
R90 = CMP-0025704-4: RES, 10, 5%, 0.25 W, AEC-Q200 Grade 0, 0603; Manufacturer: Vishay-Dale; Value: 10; Value_Code: 10R0; Power_W: 250mW; Value2: 0.25W; VDC_V: 75V; TempCo: 200 ppm/C; EIA_Code: E24; AEC Category: Q200; AEC Grade: 0; AEC Qualified: Y; SizeArea_mm2: 1.28; SizeX_mm: 1.6; SizeY_mm: 0.8; SizeZ_mm: 1
R91 R98 = CMP-0025697-4: RES, 0, 5%, 0.1 W, AEC-Q200 Grade 0, 0603; Manufacturer: Vishay-Dale; Value: 0; Value_Code: 0000; Power_W: 100mW; Value2: 0.1W; VDC_V: 75V; TempCo: 200 ppm/C; EIA_Code: E24; AEC Category: Q200; AEC Qualified: Y; SizeArea_mm2: 1.28; SizeX_mm: 1.6; SizeY_mm: 0.8; SizeZ_mm: 1
R150 = CMP-0092403-1: RES 0.0025 OHM 1% 5W 3921; Manufacturer: Vishay; AEC Grade: Grade 0; SizeZ_mm: 0.081inch; TempCo: 350ppm/°C; AEC Qualified: Yes
R248 = CMP-0026547-2: RES, 76.8 k, 1%, 0.063 W, AEC-Q200 Grade 0, 0402; Manufacturer: Vishay-Dale; Power_W: 63mW; TempCo: 100 ppm/C; Value_Code: 76k8; Value: 76.8k; EIA_Code: E96; SizeX_mm: 1; SizeY_mm: 0.5; SizeZ_mm: 0.6; Value2: 0.063W; CompType: Resistor; AEC Qualified: Y; VDC_V: 50V; AEC Category: Q200; AEC Grade: 0
R249 = CMP-0022014-4: RES, 118 k, 1%, 0.1 W, AEC-Q200 Grade 0, 0603; Manufacturer: Vishay-Dale; Power_W: 100mW; TempCo: 100 ppm/C; Value: 118k; EIA_Code: E96; SizeX_mm: 1.6; SizeY_mm: 0.8; SizeZ_mm: 1; Value2: 0.1W; SizeArea_mm2: 1.28; CompType: Resistor; AEC Qualified: Y; VDC_V: 75V; AEC Category: Q200; AEC Grade: 0
R251 = CMP-0026721-1: RES, 100 k, 1%, 0.0625 W, 0402; Manufacturer: Yageo America; Power_W: 62.5mW; TempCo: 100 ppm/C; Value_Code: 100k; U/M: EA; EIA_Code: E96; SizeX_mm: 1; SizeY_mm: 0.5; SizeZ_mm: 0.6; CompType: Resistor; AEC Qualified: N; VDC_V: 50V; AEC Category: Q200
R271 = CMP-0026721-1: RES, 100 k, 1%, 0.0625 W, 0402; Manufacturer: Yageo America; Power_W: 62.5mW; TempCo: 100 ppm/C; U/M: EA; Value: 100k; EIA_Code: E96; SizeX_mm: 1; SizeY_mm: 0.5; SizeZ_mm: 0.6; CompType: Resistor; AEC Qualified: N; VDC_V: 50V; AEC Category: Q200
RT2 = CMP-0002562-2: Thermistor NTC, 50 ohm, 25%, D12.5xH16.5mm; Manufacturer: TDK; Value: 50; TaMin_C: -40°C; TaMax_C: 125°C; U/M: EA
U7 = CMP-0081537-2: TMCS1100A1DT, D0008A (SOIC-8); Alternate Manufacturer: Texas Instruments; CompType: IC; SizeAreaWB_mm2: 56.58; SizeX_mm: 4.9; SizeY_mm: 6.2; AEC Category: Q200; SizeArea_mm2: 30.38; SizeZ_mm: 1.75; AEC Qualified: N
U8 = CMP-0066946-1: 4A/8A Single Channel High-speed Low-side Gate Driver, DBV0006A (SOT-23-6); Alternate PartNumber: UCC27511DBVT; Manufacturer: Texas Instruments; CompType: IC; U/M: EA; Green_Lifecycle: Active; Green_REACh: Passed; SizeArea_mm2: 8.12; SizeAreaWB_mm2: 14.82; SizeX_mm: 2.8; SizeY_mm: 2.9; SizeZ_mm: 1.45
U9 = CMP-0013005-2: 620-V High-Side Low-Side Gate Driver with 2.5A Peak Output and RobustDrive, D0008A (SOIC-8); Manufacturer: Texas Instruments; SizeX_mm: 4.9; SizeY_mm: 6.2; CompType: IC; SizeZ_mm: 1.75; SizeArea_mm2: 30.38; SizeAreaWB_mm2: 56.58; U/M: EA
U10 = CMP-0066771-1: 150-mA, Low-Dropout Regulator with Foldback Current Limit for Portable Devices, DBV0005A (SOT-23-5); Alternate PartNumber: TLV71333PDBVT; Alternate Manufacturer: Texas Instruments; Green_Lifecycle: Active; SizeAreaWB_mm2: 14.82; Green_REACh: Passed; U/M: EA; SizeZ_mm: 1.45; SizeX_mm: 2.8; SizeY_mm: 2.9; SizeArea_mm2: 8.12; CompType: IC
U11 = CMP-0077646-2: 4-A, 6-A, 3.0-kVRMS Isolated Dual-Channel Gate Driver, D0016B (SOIC-16); Alternate Manufacturer: Texas Instruments; SizeAreaWB_mm2: 95.2; SizeZ_mm: 1.75; SizeX_mm: 6.0; SizeY_mm: 9.9; SizeArea_mm2: 59.4; CompType: IC; AEC Qualified: N; AEC Category: Q200; Rating: Catalog
U12 = CMP-0084864-4: 2.9-V to 18-V, 4-A Synchronous Buck Converters, RPJ0009A (VQFN-HR-9); Manufacturer: Texas Instruments; Alternate PartNumber: TPS62901RPJT; SizeAreaWB_mm2: 7.5; CompType: IC; SizeY_mm: 2; SizeArea_mm2: 3; SizeZ_mm: 1; AEC Qualified: N; SizeX_mm: 1.5; AEC Category: Q200

## Sheet PMP41114_MAIN_PFC_Control.SchDoc
size 431 x 279 mm; Date: Not shown in title block; ApprovedBy: Not shown in title block; CheckedBy: Not shown in title block; Author: Not shown in title block; CompanyName: Not shown in title block; Engineer: Not shown in title block; Organization: Not shown in title block; Address1: Not shown in title block; Address2: Not shown in title block; Address3: Not shown in title block; Address4: Not shown in title block; DocumentNumber: 2; Revision: Use project parameter SCH_Rev; SheetNumber: 2; SheetTotal: 3; PageSetup: Record=PageOptions¦CenterHorizontal=True¦CenterVertical=True¦PrintScale=1.00¦XCorrection=1.00¦YCorrection=1.00¦PrintKind=0¦BorderSize=5000000¦LeftOffset=0¦BottomOffset=0¦Orientation=2¦PaperLength=1000¦PaperWidth=1000¦Scale=100¦PaperSource=15¦PrintQuality=600¦MediaType=1¦DitherType=10¦PaperKind=Letter¦PrintScaleMode=1
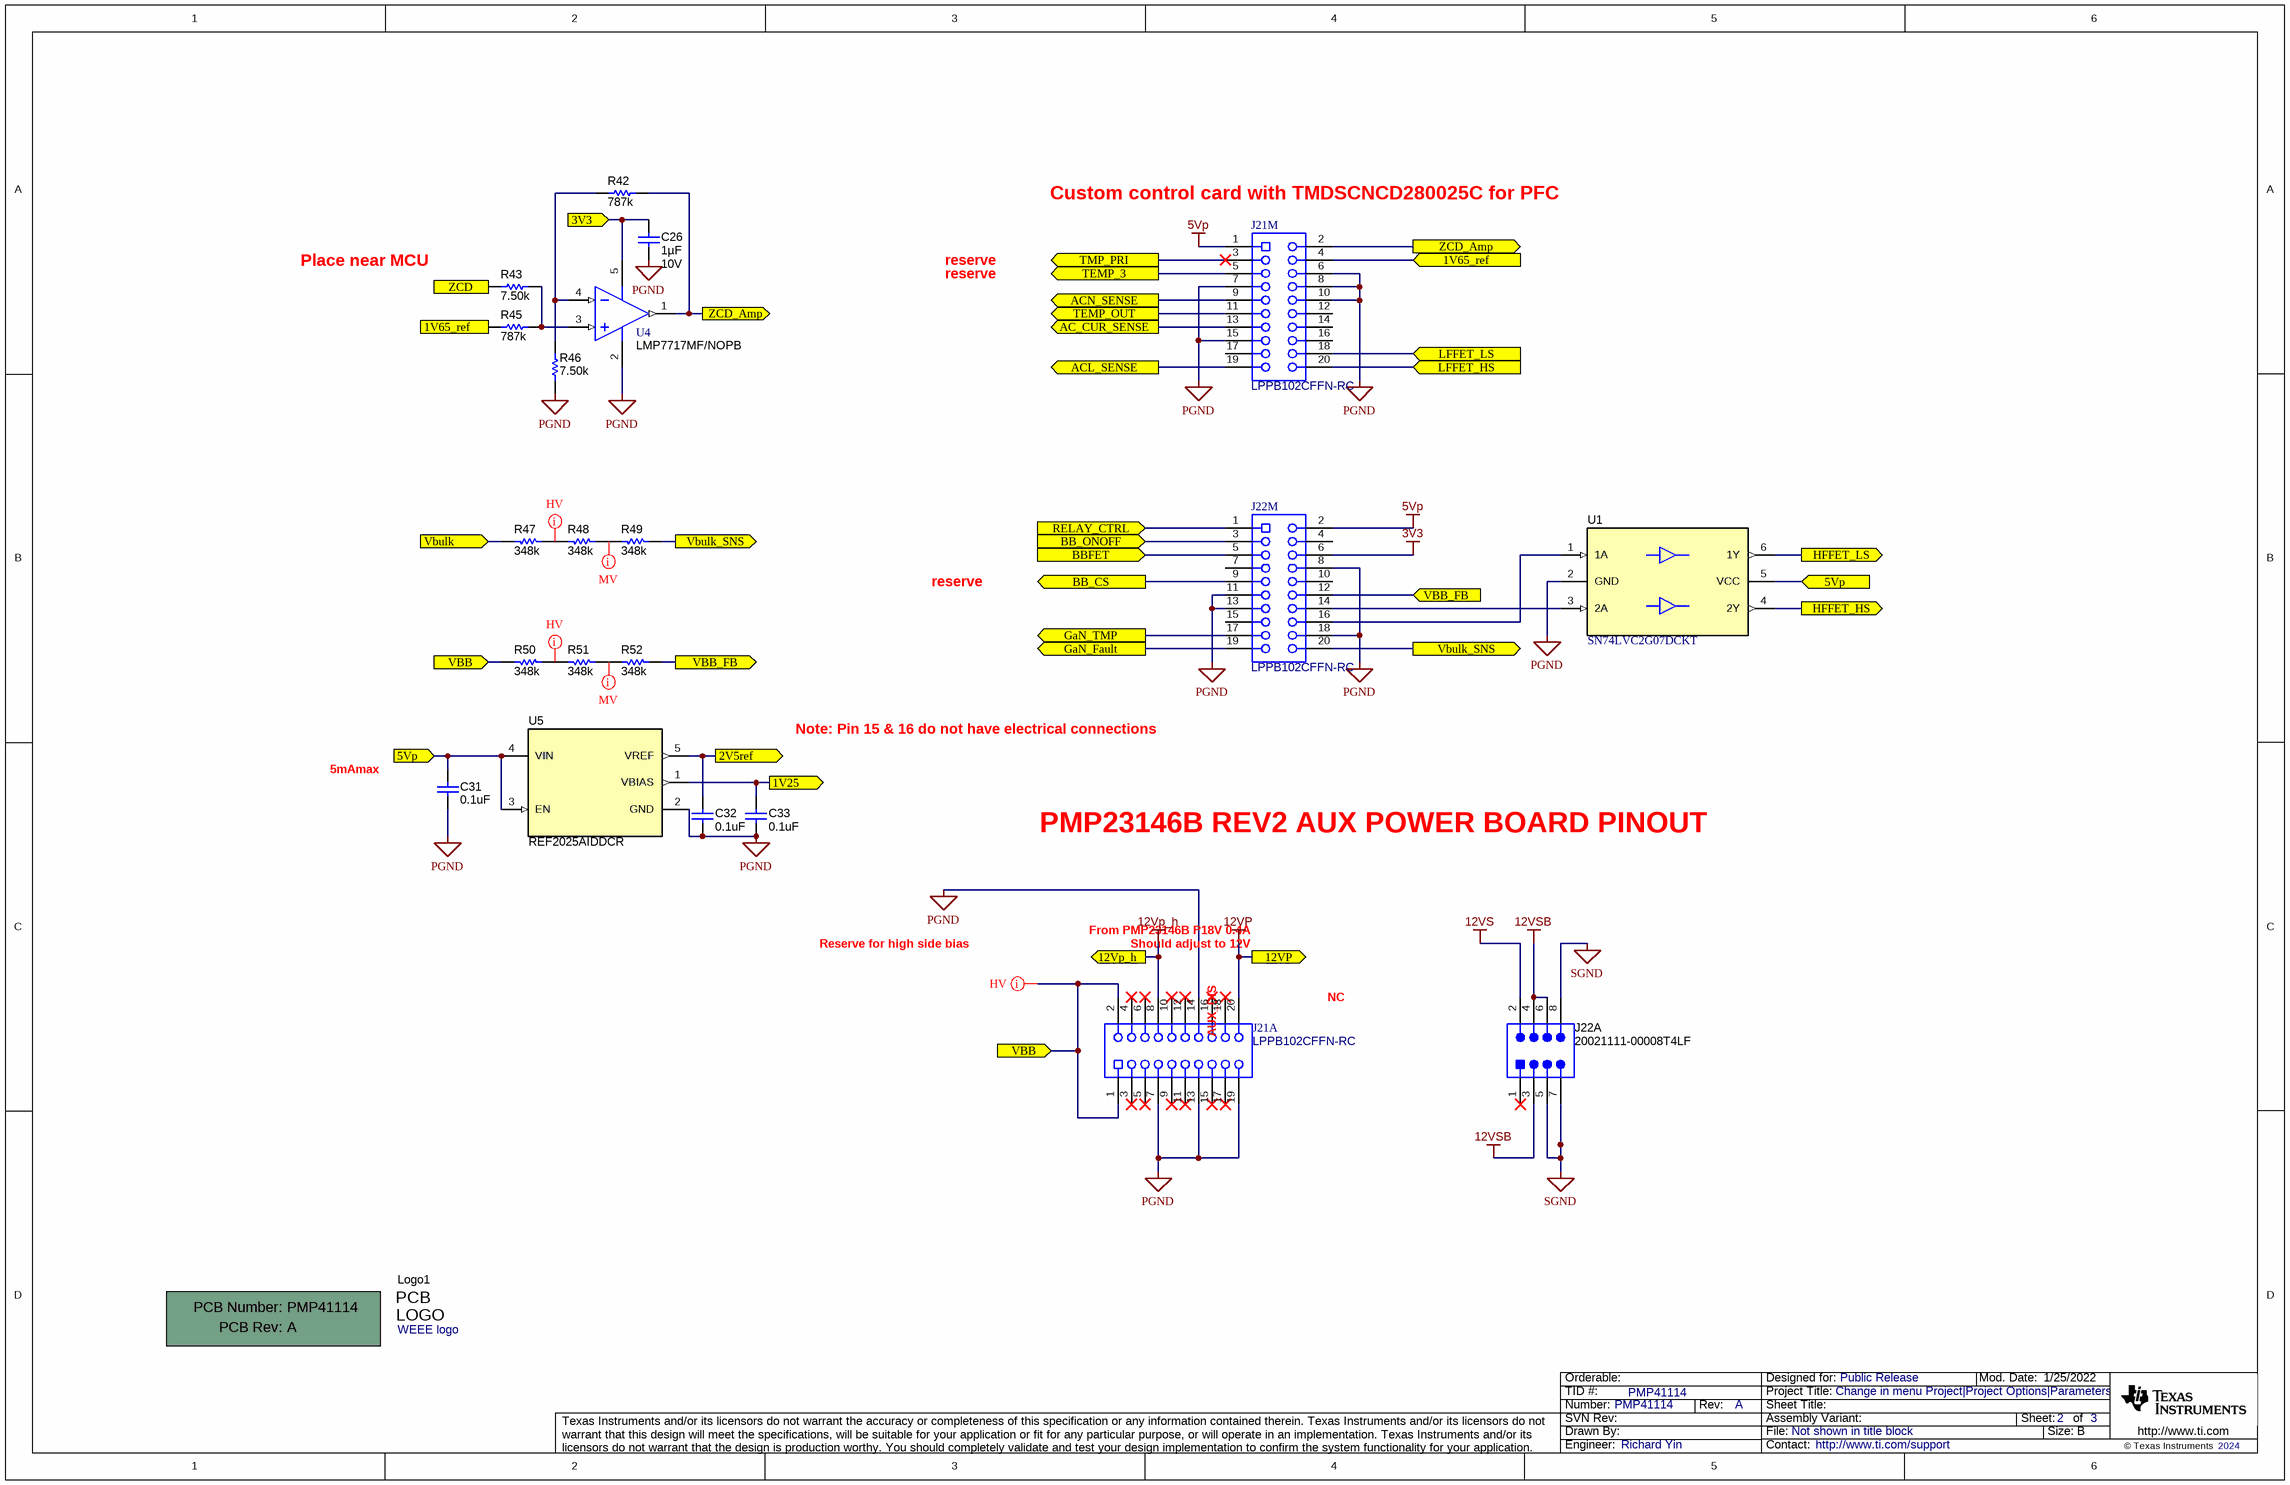
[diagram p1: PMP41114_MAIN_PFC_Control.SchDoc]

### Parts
!PCB  Printed Circuit Board  (value not drawn)  (mechanical)
C26  Cap_F: 1µF  VDC_V: 10V  [0603]  (hidden comment: LMK107B7105KA-T)
C31  ValueDisplayed: 0.1uF  [0603]  (hidden comment: 06033C104JAT2A)
C32  ValueDisplayed: 0.1uF  [0603]  (hidden comment: 06033C104JAT2A)
C33  ValueDisplayed: 0.1uF  [0603]  (hidden comment: 06033C104JAT2A)
J21A  LPPB102CFFN-RC  [Sullins_LPPB102CFFN]
J21M  LPPB102CFFN-RC  [Sullins_LPPB102CFFN]
J22A  20021111-00008T4LF  [FCI_20021111-00008xxLF]
J22M  LPPB102CFFN-RC  [Sullins_LPPB102CFFN]
Logo1  WEEE logo  [WEEE_Minimum]  (no BOM)
R42  ValueDisplayed: 787k  [0402]  (hidden comment: CRCW0402787KFKED)
R43  ValueDisplayed: 7.50k  [0402]  (hidden comment: CRCW04027K50FKED)
R45  ValueDisplayed: 787k  [0402]  (hidden comment: CRCW0402787KFKED)
R46  ValueDisplayed: 7.50k  [0402]  (hidden comment: CRCW04027K50FKED)
R47  ValueDisplayed: 348k  [1206]  (hidden comment: RC1206FR-07348KL)
R48  ValueDisplayed: 348k  [1206]  (hidden comment: RC1206FR-07348KL)
R49  ValueDisplayed: 348k  [1206]  (hidden comment: RC1206FR-07348KL)
R50  ValueDisplayed: 348k  [1206]  (hidden comment: RC1206FR-07348KL)
R51  ValueDisplayed: 348k  [1206]  (hidden comment: RC1206FR-07348KL)
R52  ValueDisplayed: 348k  [1206]  (hidden comment: RC1206FR-07348KL)
U1  SN74LVC2G07DCKT  [DCK0006A_N]
U4  LMP7717MF/NOPB  [DBV0005A_N]
U5  REF2025AIDDCR  [DDC0005A_L]

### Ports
1V25 (out), 1V65_ref (in), 2V5ref (out), 3V3 (in), 5Vp (in), 12VP (out), 12Vp_h (out), AC_CUR_SENSE (out), ACL_SENSE (out), ACN_SENSE (out), BB_CS (out), BB_ONOFF (in), BBFET (in), GaN_Fault (out), GaN_TMP (out), HFFET_HS (out), HFFET_LS (out), LFFET_HS (in), LFFET_LS (in), RELAY_CTRL (in), TEMP_3 (out), TEMP_OUT (out), TMP_PRI (out), VBB (in), VBB_FB (in), VBB_FB (out), Vbulk (in), Vbulk_SNS (out), ZCD (in), ZCD_Amp (out)

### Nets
3V3: C26.1 J22M.6 U4.5(V+) ; port 3V3
5Vp: J21M.1 J22M.2
12VP: J21A.20 ; port 12VP
12Vp_h: J21A.8 ; port 12Vp_h
12VS: J22A.2
12VSB: J22A.3 J22A.4 J22A.6
PGND: C26.2 C31.1 C32.1 C33.1 J21A.7 J21A.13 J21A.14 J21A.19 J21M.6 J21M.7 J21M.8 J21M.10 J21M.15 J22M.8 J22M.11 J22M.13 J22M.18 R46.1 U1.2(GND) U4.2(V-) U5.2(GND)
SGND: J22A.5 J22A.7 J22A.8
1V25: C33.2 U5.1(VBIAS) ; port 1V25
1V65_ref: J21M.4 R45.1 ; port 1V65_ref
2V5ref: C32.2 U5.5(VREF) ; port 2V5ref
5Vp: C31.2 U1.5(VCC) U5.3(EN) U5.4(VIN) ; port 5Vp  [a separate net that carries the same name]
AC_CUR_SENSE: J21M.13 ; port AC_CUR_SENSE
ACL_SENSE: J21M.19 ; port ACL_SENSE
ACN_SENSE: J21M.9 ; port ACN_SENSE
BB_CS: J22M.9 ; port BB_CS
BB_ONOFF: J22M.3 ; port BB_ONOFF
BBFET: J22M.5 ; port BBFET
GaN_Fault: J22M.19 ; port GaN_Fault
GaN_TMP: J22M.17 ; port GaN_TMP
HFFET_HS: U1.4(2Y) ; port HFFET_HS
HFFET_LS: U1.6(1Y) ; port HFFET_LS
LFFET_HS: J21M.20 ; port LFFET_HS
LFFET_LS: J21M.18 ; port LFFET_LS
RELAY_CTRL: J22M.1 ; port RELAY_CTRL
TEMP_3: J21M.5 ; port TEMP_3
TEMP_OUT: J21M.11 ; port TEMP_OUT
TMP_PRI: J21M.3 ; port TMP_PRI
VBB: J21A.1 J21A.2 R50.2 ; port VBB
VBB_FB: J22M.12 R52.1 ; port VBB_FB
Vbulk: R47.2 ; port Vbulk
Vbulk_SNS: J22M.20 R49.1 ; port Vbulk_SNS
ZCD: R43.1 ; port ZCD
ZCD_Amp: J21M.2 R42.2 U4.1(OUT) ; port ZCD_Amp
NetJ22M_14: J22M.14 U1.3(2A)
NetJ22M_16: J22M.16 U1.1(1A)
NetR42_1: R42.1 R46.2 U4.4(IN-)
NetR43_2: R43.2 R45.2 U4.3(IN+)
NetR47_1: R47.1 R48.2
NetR48_1: R48.1 R49.2
NetR50_1: R50.1 R51.2
NetR51_1: R51.1 R52.2

Not connected (* = marked no-connect by the designer): J21A 3* 4* 5* 6* 9* 10* 11* 12* 15* 16* 17* 18*; J21M 12 14 16 17; J22A 1*; J22M 4 7 10 15

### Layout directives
net class MV: NetR48_1, NetR51_1
net class HV: NetR47_1, NetR50_1, VBB

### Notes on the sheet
- (near J21M) Custom control card with TMDSCNCD280025C for PFC
- Place near MCU
- reserve
- (near C31) 5mAmax
- Note: Pin 15 & 16 do not have electrical connections
- PMP23146B REV2 AUX POWER BOARD PINOUT
- Reserve for high side bias
- From PMP23146B P18V 0.4A
- Should adjust to 12V
- (near J21A) AUX_DIS
- NC

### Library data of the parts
!PCB = CMP-0003618-2: Manufacturer: Any; PartNumber: PMP41114
C26 = CMP-0080632-1: CAP, CERM, 1 µF, 10 V,+/- 10%, X7R, 0603; Manufacturer: Taiyo Yuden; SizeAreaWB_mm2: 4.68; SizeArea_mm2: 1.28; AEC Qualified: N; AEC Category: Q200; Value: 1uF; TaMax_C: 125°C; SizeZ_mm: 1; Green_REACh: Incomplete; TaMin_C: -55°C; SizeY_mm: 0.8; Green_Lifecycle: Active; U/M: EA; SizeX_mm: 1.6
C31-C33 = CMP-0006752-5: as C39 on sheet PMP41114_MAIN_PFC
J21A J21M J22M = CMP-0750171-1: Receptacle, 1.27mm, 10x2, Gold, TH; Manufacturer: Sullins Connector Solutions; Gender: Female; Current_A: 1A; Cert_UL: Y; Row_Count: 2; Pitch_mm: 1.27
J22A = CMP-0065025-2: Header, 1.27mm, 4x2, Gold, TH; Manufacturer: FCI; Current_A: 1A; Shrouded: N; Gender: Male; Voltage_V: 125V; Row_Count: 2; Pitch_mm: 1.27; ContactFinish: Tin; Cert_UL: Y
Logo1 = CMP-0074769-1
R42 R45 = CMP-0026549-2: RES, 787 k, 1%, 0.063 W, AEC-Q200 Grade 0, 0402; Manufacturer: Vishay-Dale; Power_W: 63mW; TempCo: 100 ppm/C; Value: 787k; EIA_Code: E96; SizeX_mm: 1; SizeY_mm: 0.5; SizeZ_mm: 0.6; Value2: 0.063W; AEC Qualified: Y; VDC_V: 50V; AEC Category: Q200; AEC Grade: 0
R43 R46 = CMP-0026555-2: RES, 7.50 k, 1%, 0.063 W, AEC-Q200 Grade 0, 0402; Manufacturer: Vishay-Dale; Value_Code: 7k50; SizeArea_mm2: 0.5; AEC Qualified: Y; AEC Category: Q200; Res_ohm: 7.5k; Value: 7.50k; SizeZ_mm: 0.6; EIA_Code: E96; TempCo: 100 ppm/C; AEC Grade: 0; Power_W: 63mW; VDC_V: 50V; Value2: 0.063W; SizeX_mm: 1
R47-R49 = CMP-0018215-2: as R60 on sheet PMP41114_MAIN_PFC
R50-R52 = CMP-0018215-2: RES, 348 k, 1%, 0.25 W, 1206; Manufacturer: Yageo America; Power_W: 250mW; TempCo: 100 ppm/C; U/M: EA; Value: 348k; EIA_Code: E96; SizeX_mm: 3.2; SizeY_mm: 1.6; SizeZ_mm: 1.35; Value2: 0.25W; SizeArea_mm2: 5.12; CompType: Resistor; VDC_V: 200V; AEC Category: Q200
U1 = CMP-0051787-3: Dual Buffer/Driver with Open-Drain Output, DCK0006A (SOT-SC70-6); Manufacturer: Texas Instruments; Alternate PartNumber: SN74LVC2G07DCKR; Output Type: CMOS; Bits(#): 2; Input Type: CMOS/TTL; Technology Family: LVC; Schmitt Trigger: No; VCC(Max)(V): 5.5; Sub-Family: Inverting Buffer/Driver; Rating: Catalog; Output Drive (IOL/IOH)(Max)(mA): 32/-32; ICC @ Nom Voltage(Max)(mA): 0.01; VCC(Min)(V): 1.65; F @ Nom Voltage(Max)(Mhz): 150; Logic: True; Voltage(Nom)(V): 1.8,2.5,3.3,5; tpd @ Nom Voltage(Max)(ns): 8.6,4.4,3.7,2.9; AEC Category: Q200; AEC Qualified: N; CompType: IC; Green_Lifecycle: Active; Green_REACh: Passed; SizeAreaWB_mm2: 9.3; SizeArea_mm2: 4.2; SizeX_mm: 2.1; SizeY_mm: 2.0; SizeZ_mm: 1.1
U4 = CMP-0068676-2: 88 MHz, Precision, Low Noise, 1.8V CMOS Input, Decompensated Operational Amplifier, DBV0005A (SOT-23-5); Manufacturer: Texas Instruments; CompType: IC; AEC Category: Q200; AEC Qualified: N; Rating: Catalog; SizeAreaWB_mm2: 14.82; SizeArea_mm2: 8.12; SizeX_mm: 2.8; SizeY_mm: 2.9; SizeZ_mm: 1.45
U5 = CMP-0076429-1: 8 ppm/degC Drift, Low-Power, Dual-Output Vref and Vref/2 Voltage Reference, DDC0005A (SOT-23-T-5); Manufacturer: Texas Instruments; Alternate PartNumber: REF2025AIDDCT; SizeAreaWB_mm2: 14.82; SizeArea_mm2: 8.12; SizeZ_mm: 1.1; SizeY_mm: 2.9; U/M: EA; CompType: IC; SizeX_mm: 2.8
